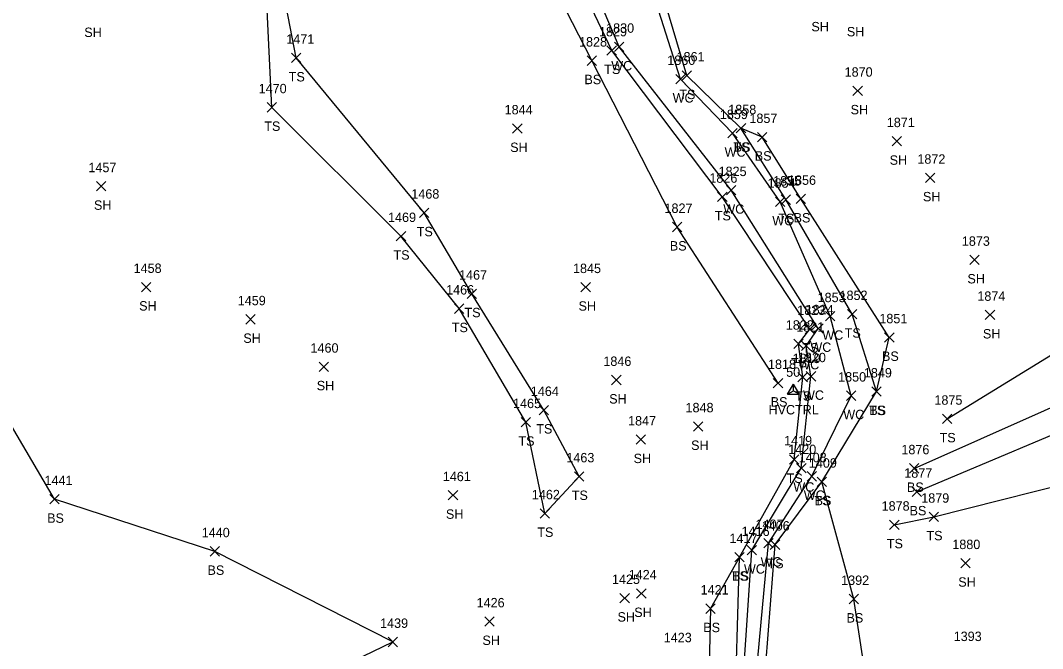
# Model space of a CAD drawing. Extents: x 1754529 to 1755810, y 621660 to 624656.
# Drawn here: x 1755027.6 to 1755244.8, y 624086.9 to 624220.4 of the extents above; entities that cross this region are included whole.
import ezdxf

# ---------------------------------------------------------------- set-up
doc = ezdxf.new("R2010")
doc.units = 0
for name, color, linetype in [('C_A', 7, 'Continuous'), ('C_I', 7, 'Continuous'), ('CPSM', 7, 'Continuous'), ('L_A', 7, 'Continuous'), ('L_I', 7, 'Continuous'), ('L_TIC', 7, 'Continuous'), ('LAWE', 7, 'Continuous'), ('LELB', 7, 'Continuous')]:
    doc.layers.add(name, color=color, linetype=linetype)

msp = doc.modelspace()

# ---------------------------------------------------------------- linework, layer by layer
at = {"layer": 'CPSM'}
for p, q in [((1755190.63, 624140.93), (1755191.88, 624143.1)), ((1755193.13, 624140.93), (1755191.88, 624143.1)), ((1755191.88, 624141.65), (1755191.88, 624143.1)), ((1755190.63, 624140.93), (1755191.88, 624141.65)), ((1755190.63, 624140.93), (1755193.13, 624140.93)), ((1755191.88, 624141.65), (1755191.88, 624141.65)), ((1755191.88, 624141.65), (1755193.13, 624140.93))]:
    msp.add_line(p, q, dxfattribs=at)
at = {"layer": 'L_TIC'}
for points in [[(1755152.26, 624213.03), (1755154.26, 624215.03)], [(1755154.26, 624213.03), (1755152.26, 624215.03)], [(1755153.86, 624213.79), (1755155.86, 624215.79)], [(1755155.86, 624213.79), (1755153.86, 624215.79)], [(1755085.23, 624211.44), (1755087.23, 624213.44)], [(1755087.23, 624211.44), (1755085.23, 624213.44)], [(1755148.02, 624210.86), (1755150.02, 624212.86)], [(1755150.02, 624210.86), (1755148.02, 624212.86)], [(1755166.9, 624206.95), (1755168.9, 624208.95)], [(1755168.9, 624206.95), (1755166.9, 624208.95)], [(1755168.22, 624207.69), (1755170.22, 624209.69)], [(1755170.22, 624207.69), (1755168.22, 624209.69)], [(1755204.53, 624204.45), (1755206.53, 624206.45)], [(1755206.53, 624204.45), (1755204.53, 624206.45)], [(1755080.03, 624200.93), (1755082.03, 624202.93)], [(1755082.03, 624200.93), (1755080.03, 624202.93)], [(1755132.21, 624196.44), (1755134.21, 624198.44)], [(1755134.21, 624196.44), (1755132.21, 624198.44)], [(1755177.94, 624195.44), (1755179.94, 624197.44)], [(1755179.94, 624195.44), (1755177.94, 624197.44)], [(1755179.73, 624196.48), (1755181.73, 624198.48)], [(1755181.73, 624196.48), (1755179.73, 624198.48)], [(1755179.73, 624196.48), (1755181.73, 624198.48)], [(1755181.73, 624196.48), (1755179.73, 624198.48)], [(1755184.21, 624194.61), (1755186.21, 624196.61)], [(1755186.21, 624194.61), (1755184.21, 624196.61)], [(1755212.84, 624193.73), (1755214.84, 624195.73)], [(1755214.84, 624193.73), (1755212.84, 624195.73)], [(1755219.9, 624185.95), (1755221.9, 624187.95)], [(1755221.9, 624185.95), (1755219.9, 624187.95)], [(1755043.77, 624184.15), (1755045.77, 624186.15)], [(1755045.77, 624184.15), (1755043.77, 624186.15)], [(1755177.66, 624183.32), (1755179.66, 624185.32)], [(1755179.66, 624183.32), (1755177.66, 624185.32)], [(1755175.76, 624181.9), (1755177.76, 624183.9)], [(1755177.76, 624181.9), (1755175.76, 624183.9)], [(1755188.07, 624180.84), (1755190.07, 624182.84)], [(1755190.07, 624180.84), (1755188.07, 624182.84)], [(1755189.25, 624181.31), (1755191.25, 624183.31)], [(1755191.25, 624181.31), (1755189.25, 624183.31)], [(1755192.46, 624181.46), (1755194.46, 624183.46)], [(1755194.46, 624181.46), (1755192.46, 624183.46)], [(1755112.43, 624178.53), (1755114.43, 624180.53)], [(1755114.43, 624178.53), (1755112.43, 624180.53)], [(1755107.49, 624173.55), (1755109.49, 624175.55)], [(1755109.49, 624173.55), (1755107.49, 624175.55)], [(1755166.17, 624175.49), (1755168.17, 624177.49)], [(1755168.17, 624175.49), (1755166.17, 624177.49)], [(1755229.35, 624168.5), (1755231.35, 624170.5)], [(1755231.35, 624168.5), (1755229.35, 624170.5)], [(1755053.37, 624162.73), (1755055.37, 624164.73)], [(1755055.37, 624162.73), (1755053.37, 624164.73)], [(1755146.73, 624162.7), (1755148.73, 624164.7)], [(1755148.73, 624162.7), (1755146.73, 624164.7)], [(1755122.57, 624161.31), (1755124.57, 624163.31)], [(1755124.57, 624161.31), (1755122.57, 624163.31)], [(1755119.88, 624158.14), (1755121.88, 624160.14)], [(1755121.88, 624158.14), (1755119.88, 624160.14)], [(1755198.7, 624156.52), (1755200.7, 624158.52)], [(1755200.7, 624156.52), (1755198.7, 624158.52)], [(1755203.36, 624156.97), (1755205.36, 624158.97)], [(1755205.36, 624156.97), (1755203.36, 624158.97)], [(1755232.64, 624156.8), (1755234.64, 624158.8)], [(1755234.64, 624156.8), (1755232.64, 624158.8)], [(1755075.51, 624155.86), (1755077.51, 624157.86)], [(1755077.51, 624155.86), (1755075.51, 624157.86)], [(1755196.16, 624153.94), (1755198.16, 624155.94)], [(1755198.16, 624153.94), (1755196.16, 624155.94)], [(1755194.38, 624153.8), (1755196.38, 624155.8)], [(1755196.38, 624153.8), (1755194.38, 624155.8)], [(1755211.25, 624152.03), (1755213.25, 624154.03)], [(1755213.25, 624152.03), (1755211.25, 624154.03)], [(1755191.95, 624150.67), (1755193.95, 624152.67)], [(1755193.95, 624150.67), (1755191.95, 624152.67)], [(1755193.59, 624150.24), (1755195.59, 624152.24)], [(1755195.59, 624150.24), (1755193.59, 624152.24)], [(1755091.1, 624145.78), (1755093.1, 624147.78)], [(1755093.1, 624145.78), (1755091.1, 624147.78)], [(1755192.84, 624143.56), (1755194.84, 624145.56)], [(1755194.84, 624143.56), (1755192.84, 624145.56)], [(1755194.6, 624143.75), (1755196.6, 624145.75)], [(1755196.6, 624143.75), (1755194.6, 624145.75)], [(1755153.24, 624142.96), (1755155.24, 624144.96)], [(1755155.24, 624142.96), (1755153.24, 624144.96)], [(1755187.6, 624142.32), (1755189.6, 624144.32)], [(1755189.6, 624142.32), (1755187.6, 624144.32)], [(1755203.15, 624139.63), (1755205.15, 624141.63)], [(1755205.15, 624139.63), (1755203.15, 624141.63)], [(1755208.55, 624140.51), (1755210.55, 624142.51)], [(1755210.55, 624140.51), (1755208.55, 624142.51)], [(1755208.55, 624140.51), (1755210.55, 624142.51)], [(1755210.55, 624140.51), (1755208.55, 624142.51)], [(1755137.82, 624136.58), (1755139.82, 624138.58)], [(1755139.82, 624136.58), (1755137.82, 624138.58)], [(1755223.52, 624134.71), (1755225.52, 624136.71)], [(1755225.52, 624134.71), (1755223.52, 624136.71)], [(1755134.04, 624133.99), (1755136.04, 624135.99)], [(1755136.04, 624133.99), (1755134.04, 624135.99)], [(1755170.64, 624133.1), (1755172.64, 624135.1)], [(1755172.64, 624133.1), (1755170.64, 624135.1)], [(1755158.43, 624130.3), (1755160.43, 624132.3)], [(1755160.43, 624130.3), (1755158.43, 624132.3)], [(1755191.02, 624126.09), (1755193.02, 624128.09)], [(1755193.02, 624126.09), (1755191.02, 624128.09)], [(1755192.55, 624124.22), (1755194.55, 624126.22)], [(1755194.55, 624124.22), (1755192.55, 624126.22)], [(1755216.55, 624124.18), (1755218.55, 624126.18)], [(1755218.55, 624124.18), (1755216.55, 624126.18)], [(1755145.37, 624122.46), (1755147.37, 624124.46)], [(1755147.37, 624122.46), (1755145.37, 624124.46)], [(1755194.76, 624122.49), (1755196.76, 624124.49)], [(1755196.76, 624122.49), (1755194.76, 624124.49)], [(1755196.92, 624121.33), (1755198.92, 624123.33)], [(1755198.92, 624121.33), (1755196.92, 624123.33)], [(1755196.92, 624121.33), (1755198.92, 624123.33)], [(1755198.92, 624121.33), (1755196.92, 624123.33)], [(1755217.11, 624119.19), (1755219.11, 624121.19)], [(1755219.11, 624119.19), (1755217.11, 624121.19)], [(1755033.87, 624117.61), (1755035.87, 624119.61)], [(1755035.87, 624117.61), (1755033.87, 624119.61)], [(1755118.55, 624118.46), (1755120.55, 624120.46)], [(1755120.55, 624118.46), (1755118.55, 624120.46)], [(1755138.04, 624114.61), (1755140.04, 624116.61)], [(1755140.04, 624114.61), (1755138.04, 624116.61)], [(1755138.04, 624114.61), (1755140.04, 624116.61)], [(1755140.04, 624114.61), (1755138.04, 624116.61)], [(1755220.73, 624113.88), (1755222.73, 624115.88)], [(1755222.73, 624113.88), (1755220.73, 624115.88)], [(1755212.31, 624112.19), (1755214.31, 624114.19)], [(1755214.31, 624112.19), (1755212.31, 624114.19)], [(1755185.59, 624108.3), (1755187.59, 624110.3)], [(1755187.59, 624108.3), (1755185.59, 624110.3)], [(1755067.94, 624106.54), (1755069.94, 624108.54)], [(1755069.94, 624106.54), (1755067.94, 624108.54)], [(1755182.04, 624106.8), (1755184.04, 624108.8)], [(1755184.04, 624106.8), (1755182.04, 624108.8)], [(1755186.96, 624107.96), (1755188.96, 624109.96)], [(1755188.96, 624107.96), (1755186.96, 624109.96)], [(1755179.41, 624105.3), (1755181.41, 624107.3)], [(1755181.41, 624105.3), (1755179.41, 624107.3)], [(1755179.41, 624105.3), (1755181.41, 624107.3)], [(1755181.41, 624105.3), (1755179.41, 624107.3)], [(1755227.41, 624104.02), (1755229.41, 624106.02)], [(1755229.41, 624104.02), (1755227.41, 624106.02)], [(1755158.56, 624097.58), (1755160.56, 624099.58)], [(1755160.56, 624097.58), (1755158.56, 624099.58)], [(1755155.02, 624096.6), (1755157.02, 624098.6)], [(1755157.02, 624096.6), (1755155.02, 624098.6)], [(1755203.71, 624096.4), (1755205.71, 624098.4)], [(1755205.71, 624096.4), (1755203.71, 624098.4)], [(1755173.28, 624094.36), (1755175.28, 624096.36)], [(1755175.28, 624094.36), (1755173.28, 624096.36)], [(1755126.31, 624091.63), (1755128.31, 624093.63)], [(1755128.31, 624091.63), (1755126.31, 624093.63)], [(1755105.75, 624087.27), (1755107.75, 624089.27)], [(1755107.75, 624087.27), (1755105.75, 624089.27)]]:
    msp.add_lwpolyline(points, dxfattribs=at)
at = {"layer": 'LAWE'}
for points in [[(1755173.74, 623956.25), (1755179.49, 623981.26), (1755189.19, 624018.36), (1755179.71, 624027.81), (1755177.17, 624037.31), (1755183.05, 624071.07), (1755186.59, 624109.3), (1755195.76, 624123.49), (1755204.15, 624140.63), (1755199.7, 624157.52), (1755189.07, 624181.84), (1755178.94, 624196.44), (1755167.9, 624207.95), (1755156.07, 624245.11), (1755149.51, 624271.99), (1755152.32, 624294.92), (1755143.66, 624313.83), (1755149.45, 624329.22), (1755168.42, 624354.45), (1755209.86, 624368.35), (1755209.13, 624369.86)], [(1755172.44, 623956.64), (1755176.98, 623981.31), (1755183.44, 624014.66), (1755174.17, 624039.77), (1755180.5, 624069.56), (1755183.04, 624107.8), (1755193.55, 624125.22), (1755195.6, 624144.75), (1755194.59, 624151.24), (1755197.16, 624154.94), (1755178.66, 624184.32), (1755154.86, 624214.79), (1755145.09, 624237.93), (1755132.18, 624249.28), (1755138.85, 624266.04), (1755143.77, 624297.7), (1755137.75, 624306.01)]]:
    msp.add_lwpolyline(points, dxfattribs=at)
at = {"layer": 'LELB'}
for points in [[(1755139.04, 624115.61), (1755146.37, 624123.46), (1755138.82, 624137.58), (1755123.57, 624162.31), (1755113.43, 624179.53), (1755086.23, 624212.44), (1755082.86, 624229.74), (1755080.02, 624248.74), (1755085.06, 624291.34), (1755077.56, 624309.64), (1755080.76, 624337.28), (1755079.75, 624370.72), (1755071.03, 624399.94), (1755077.76, 624423.68)], [(1755139.04, 624115.61), (1755135.04, 624134.99), (1755120.88, 624159.14), (1755108.49, 624174.55), (1755081.03, 624201.93), (1755079.94, 624225.73), (1755076.51, 624247.96), (1755080.69, 624289.64), (1755074.01, 624309.47), (1755073.93, 624332.78), (1755077.13, 624367.68), (1755065.05, 624394.38), (1755036.59, 624410.3), (1755018.14, 624419.38)], [(1755179.93, 623958.52), (1755184.68, 623980.7), (1755191.18, 624019.58), (1755181.19, 624028.74), (1755178.62, 624037.28), (1755185, 624070.71), (1755187.96, 624108.96), (1755197.92, 624122.33), (1755209.55, 624141.51), (1755204.36, 624157.97), (1755190.25, 624182.31), (1755180.73, 624197.48), (1755169.22, 624208.69), (1755158.15, 624245.97), (1755151.05, 624272.57), (1755153.5, 624295.6), (1755146.12, 624314.43), (1755150.89, 624328.89), (1755170.15, 624351.46)], [(1755188.6, 624143.32), (1755167.17, 624176.49), (1755149.02, 624211.86), (1755135.31, 624238.73), (1755132.18, 624249.28)], [(1755170.6, 623960.85), (1755174.73, 623982.17), (1755180.73, 624013.57), (1755171.3, 624040.04), (1755179.35, 624069.6), (1755180.41, 624106.3), (1755192.02, 624127.09), (1755193.84, 624144.56), (1755192.95, 624151.67), (1755195.38, 624154.8), (1755176.76, 624182.9), (1755153.26, 624214.03), (1755142.49, 624236.72), (1755135.31, 624238.73)], [(1755209.55, 624141.51), (1755212.25, 624153.03), (1755193.46, 624182.46), (1755185.21, 624195.61), (1755180.73, 624197.48)], [(1755224.52, 624135.71), (1755254.61, 624154.2), (1755280.26, 624179.83)], [(1755217.55, 624125.18), (1755259.36, 624143.82), (1755292.22, 624168.58)], [(1755218.11, 624120.19), (1755260.79, 624138.16), (1755298.07, 624154.88), (1755292.22, 624168.58)], [(1755180.41, 624106.3), (1755174.28, 624095.36), (1755173.76, 624074.16), (1755124.51, 624068.87), (1755100.91, 624059), (1755087.06, 624039), (1755072.75, 624037.25), (1755062.63, 624048.39), (1755087.97, 624079.2), (1755106.75, 624088.27), (1755068.94, 624107.54), (1755034.87, 624118.61), (1755022.08, 624140.4), (1755014.83, 624155.53)], [(1755213.31, 624113.19), (1755221.73, 624114.88), (1755257.64, 624123.92), (1755307.67, 624133.57)], [(1755286.2, 623944.29), (1755267.63, 623949.34), (1755239.18, 623957.43), (1755232.04, 623971.1), (1755221.75, 623997.22), (1755207.57, 624028.22), (1755193.15, 624052.21), (1755209.59, 624065.41), (1755204.71, 624097.4), (1755197.92, 624122.33)]]:
    msp.add_lwpolyline(points, dxfattribs=at)

# ---------------------------------------------------------------- texts
at = {"layer": 'C_A'}
msp.add_text('HVCTRL', height=2, dxfattribs=at).set_placement((1755186.57, 624136.65))
at = {"layer": 'C_I'}
msp.add_text('50', height=2, dxfattribs=at).set_placement((1755190.33, 624144.65))
at = {"layer": 'L_A'}
for s, p in [('SH', (1755041.2, 624216.89)), ('SH', (1755195.69, 624218.09)), ('SH', (1755203.23, 624217.02)), ('TS', (1755151.67, 624209.03)), ('WC', (1755153.17, 624209.79)), ('TS', (1755084.64, 624207.44)), ('BS', (1755147.46, 624206.86)), ('WC', (1755166.21, 624202.95)), ('TS', (1755167.63, 624203.69)), ('SH', (1755204.02, 624200.45)), ('TS', (1755079.44, 624196.93)), ('SH', (1755131.69, 624192.44)), ('WC', (1755177.25, 624191.44)), ('TS', (1755179.14, 624192.48)), ('BS', (1755179.17, 624192.48)), ('BS', (1755183.66, 624190.61)), ('SH', (1755212.32, 624189.73)), ('SH', (1755043.26, 624180.15)), ('SH', (1755219.39, 624181.95)), ('TS', (1755175.17, 624177.9)), ('WC', (1755176.97, 624179.32)), ('WC', (1755187.38, 624176.84)), ('TS', (1755188.66, 624177.31)), ('BS', (1755191.91, 624177.46)), ('TS', (1755111.84, 624174.53)), ('BS', (1755165.61, 624171.49)), ('TS', (1755106.9, 624169.55)), ('SH', (1755228.84, 624164.5)), ('SH', (1755052.86, 624158.73)), ('SH', (1755146.22, 624158.7)), ('TS', (1755121.98, 624157.31)), ('TS', (1755119.29, 624154.14)), ('SH', (1755075, 624151.86)), ('WC', (1755198.01, 624152.52)), ('TS', (1755202.77, 624152.97)), ('SH', (1755232.13, 624152.8)), ('TS', (1755193.79, 624149.8)), ('WC', (1755195.47, 624149.94)), ('BS', (1755210.69, 624148.03)), ('TS', (1755191.36, 624146.67)), ('WC', (1755192.9, 624146.24)), ('SH', (1755090.59, 624141.78)), ('SH', (1755152.73, 624138.96)), ('TS', (1755192.25, 624139.56)), ('WC', (1755193.91, 624139.75)), ('BS', (1755187.04, 624138.32)), ('TS', (1755207.96, 624136.51)), ('BS', (1755207.99, 624136.51)), ('WC', (1755202.46, 624135.63)), ('TS', (1755137.23, 624132.58)), ('TS', (1755133.45, 624129.99)), ('TS', (1755222.93, 624130.71)), ('SH', (1755170.13, 624129.1)), ('SH', (1755157.92, 624126.3)), ('TS', (1755190.43, 624122.09)), ('WC', (1755191.86, 624120.22)), ('BS', (1755215.99, 624120.18)), ('TS', (1755144.78, 624118.46)), ('WC', (1755194.07, 624118.49)), ('TS', (1755196.33, 624117.33)), ('BS', (1755196.37, 624117.33)), ('BS', (1755216.55, 624115.19)), ('BS', (1755033.31, 624113.61)), ('SH', (1755118.04, 624114.46)), ('TS', (1755137.45, 624110.61)), ('TS', (1755137.45, 624110.61)), ('TS', (1755220.14, 624109.88)), ('TS', (1755211.72, 624108.19)), ('WC', (1755184.9, 624104.3)), ('TS', (1755186.37, 624103.96)), ('BS', (1755067.38, 624102.54)), ('WC', (1755181.35, 624102.8)), ('TS', (1755178.82, 624101.3)), ('BS', (1755178.85, 624101.3)), ('SH', (1755226.9, 624100.02)), ('SH', (1755158.05, 624093.58)), ('SH', (1755154.5, 624092.6)), ('BS', (1755203.15, 624092.4)), ('BS', (1755172.72, 624090.36)), ('SH', (1755125.8, 624087.63))]:
    msp.add_text(s, height=2, dxfattribs=at).set_placement(p)
at = {"layer": 'L_I'}
for s, p in [('1829', (1755150.56, 624217.03)), ('1830', (1755152.08, 624217.79)), ('1471', (1755084.11, 624215.44)), ('1828', (1755146.32, 624214.86)), ('1860', (1755165.07, 624210.95)), ('1861', (1755167.04, 624211.69)), ('1870', (1755202.75, 624208.45)), ('1470', (1755078.25, 624204.93)), ('1844', (1755130.51, 624200.44)), ('1859', (1755176.24, 624199.44)), ('1858', (1755178.03, 624200.48)), ('1858', (1755178.03, 624200.48)), ('1857', (1755182.52, 624198.61)), ('1871', (1755211.71, 624197.73)), ('1872', (1755218.21, 624189.95)), ('1457', (1755042.08, 624188.15)), ('1825', (1755175.97, 624187.32)), ('1826', (1755174.01, 624185.9)), ('1854', (1755186.38, 624184.84)), ('1855', (1755187.56, 624185.31)), ('1856', (1755190.72, 624185.46)), ('1468', (1755110.69, 624182.53)), ('1827', (1755164.48, 624179.49)), ('1469', (1755105.74, 624177.55)), ('1873', (1755227.66, 624172.5)), ('1458', (1755051.68, 624166.73)), ('1467', (1755120.83, 624165.31)), ('1845', (1755145.04, 624166.7)), ('1466', (1755118.08, 624162.14)), ('1853', (1755197.01, 624160.52)), ('1852', (1755201.67, 624160.97)), ('1874', (1755230.95, 624160.8)), ('1459', (1755073.81, 624159.86)), ('1823', (1755192.69, 624157.8)), ('1824', (1755194.47, 624157.94)), ('1851', (1755210.13, 624156.03)), ('1822', (1755190.26, 624154.67)), ('1821', (1755192.47, 624154.24)), ('1460', (1755089.27, 624149.78)), ('1819', (1755191.7, 624147.56)), ('1820', (1755192.82, 624147.75)), ('1846', (1755151.49, 624146.96)), ('1818', (1755186.47, 624146.32)), ('1850', (1755201.37, 624143.63)), ('1849', (1755206.84, 624144.51)), ('1849', (1755206.84, 624144.51)), ('1464', (1755136.08, 624140.58)), ('1875', (1755221.83, 624138.71)), ('1465', (1755132.3, 624137.99)), ('1848', (1755168.95, 624137.1)), ('1847', (1755156.74, 624134.3)), ('1419', (1755189.89, 624130.09)), ('1420', (1755190.77, 624128.22)), ('1876', (1755214.81, 624128.18)), ('1463', (1755143.63, 624126.46)), ('1408', (1755192.99, 624126.49)), ('1409', (1755195.15, 624125.33)), ('1409', (1755195.15, 624125.33)), ('1441', (1755032.75, 624121.61)), ('1461', (1755117.38, 624122.46)), ('1877', (1755215.42, 624123.19)), ('1462', (1755136.3, 624118.61)), ('1462', (1755136.3, 624118.61)), ('1879', (1755219.03, 624117.88)), ('1878', (1755210.61, 624116.19)), ('1440', (1755066.16, 624110.54)), ('1416', (1755180.86, 624110.8)), ('1407', (1755183.82, 624112.3)), ('1406', (1755185.13, 624111.96)), ('1417', (1755178.28, 624109.3)), ('1417', (1755178.28, 624109.3)), ('1880', (1755225.63, 624108.02)), ('1425', (1755153.32, 624100.6)), ('1424', (1755156.87, 624101.58)), ('1392', (1755202.01, 624100.4)), ('1421', (1755172.15, 624098.36)), ('1426', (1755124.56, 624095.63)), ('1439', (1755104.05, 624091.27)), ('1423', (1755164.32, 624088.22)), ('1393', (1755225.92, 624088.47))]:
    msp.add_text(s, height=2, dxfattribs=at).set_placement(p)

doc.saveas('drawing.dxf')
